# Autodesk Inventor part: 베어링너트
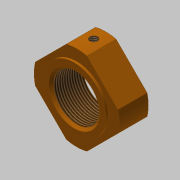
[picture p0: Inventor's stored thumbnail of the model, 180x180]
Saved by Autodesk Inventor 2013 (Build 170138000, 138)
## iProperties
Created: 2019-05
Part Number: 베어링너트
Material: 스테인리스강
Document SubType Name: Modeling
Designer: mduedu
Density: 1 g/cm^3
Author: mduedu
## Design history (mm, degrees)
sketch "스케치1"
  geometry: C1 r 17.5 at (0, 0); 1 further point
  constraints: 1 centre point, 1 coincident
  dimensions: "d0" = 35 diameter of C1
extrude "돌출1" new body sketch "스케치1" distance "d1" = 12; taper "d2" = 0 deg
sketch "스케치2"
  geometry: L1 (-21.213, 0)-(0, 21.213); L2 (0, 21.213)-(21.213, 0); L3 (21.213, 0)-(0, -21.213); L4 (0, -21.213)-(-21.213, 0); L5 (-21.213, 0)-(21.213, 0); L6 (0, 21.213)-(0, -21.213); 1 further point
  constraints: 12 end point, 2 midpoint, 2 parallel, 1 perpendicular, 1 vertical
  dimensions: "d3" = 30 distance of L1.end L2.end; "d5" = 30 distance of L2.end L3.end
extrude "돌출2" sketch "스케치2" stored distance "d6" = 12; taper "d7" = 0 deg
sketch "스케치3"
  geometry: C1 r 13 at (0, 0); 1 further point
  constraints: 1 centre point, 1 coincident
  dimensions: "d8" = 26 diameter of C1
extrude "돌출3" join sketch "스케치3" distance "d9" = 1; taper "d10" = 0 deg
hole "구멍1" diameter "d13" = 18.917; stored, may be unused: countersink angle "d17" = 90 deg, drill point angle "d19" = 118 deg; dims "d11" = 10, "d12" = 10, "d14" = 6, "d15" = 4, "d16" = 2, "d18" = 8
chamfer "모따기1" distance "d20" = 1; stored, may be unused: second distance "d21" = 2, angle "d22" = 45 deg
node "작업 평면1"
sketch "스케치5"
  geometry: L1 (-4.233, 0)-(4.233, 0) reference; 3 further points
  constraints: 1 midpoint, 1 vertical alignment
  dimensions: "d31" = 5 distance from line of point (0, 5) L1
hole "구멍3" sketch "스케치5" at (0, 5) diameter "d32" = 3.242; stored, may be unused: countersink angle "d36" = 90 deg, drill point angle "d38" = 118 deg; dims "d33" = 6, "d34" = 4, "d35" = 2, "d37" = 8
node "솔리드1"
